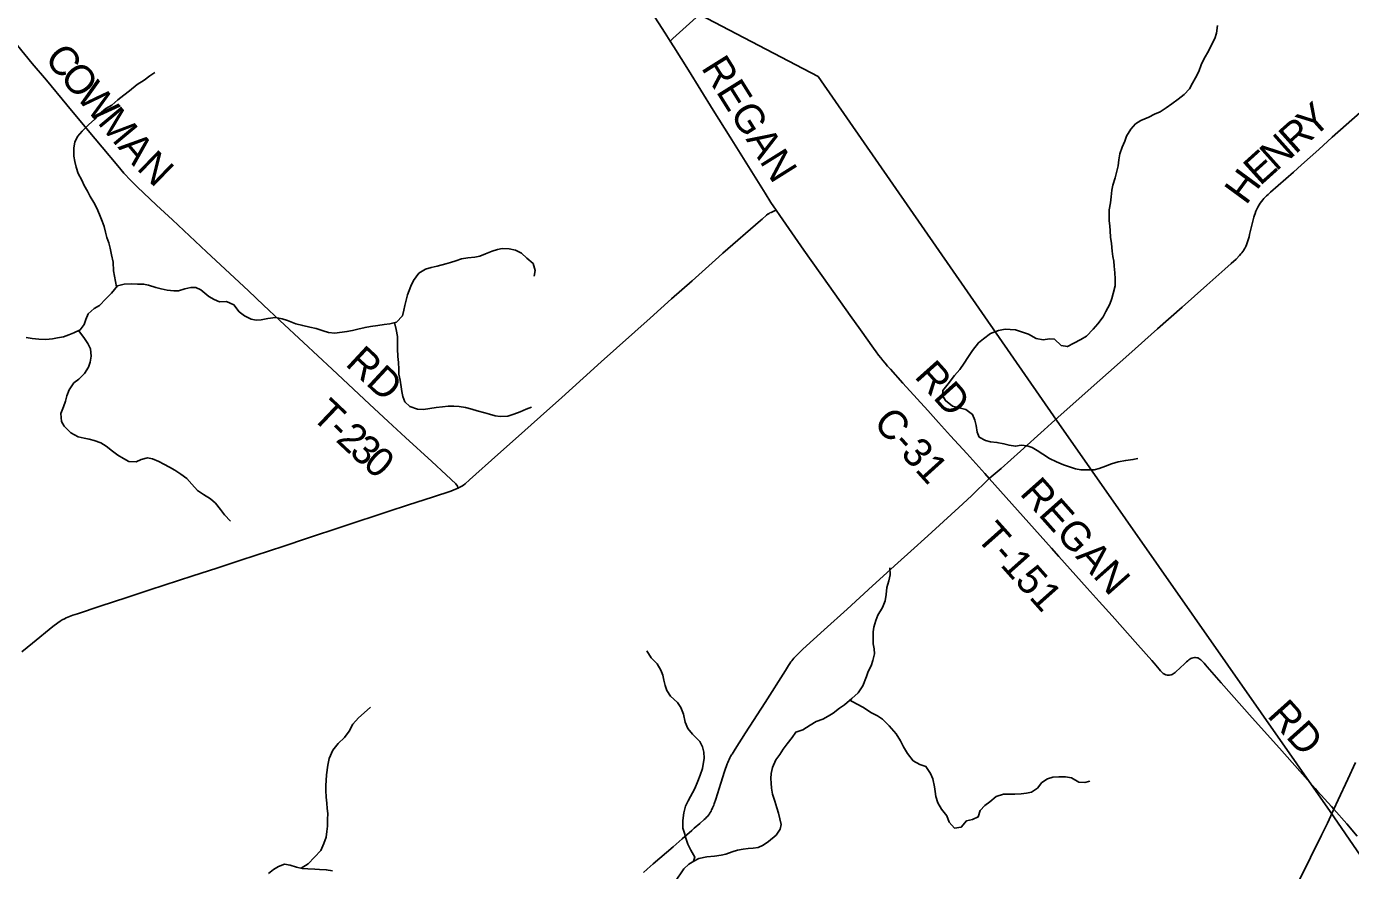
# Model space of a CAD drawing. Extents: x 1442749 to 1756758, y 235267 to 677782.
# Drawn here: x 1623834 to 1637496, y 509882 to 518590 of the extents above; entities that cross this region are included whole.
import ezdxf

# ---------------------------------------------------------------- set-up
doc = ezdxf.new("R2010")
doc.units = 0
for name, color, linetype in [('GM_X_County_Road', 7, 'Continuous'), ('GM_X_County_Road_Text', 7, 'Continuous'), ('GM_X_Minor_River', 7, 'Continuous'), ('GM_X_State_Route', 7, 'Continuous'), ('GM_X_Township', 7, 'Continuous'), ('GM_X_Township_Road', 7, 'Continuous'), ('GM_X_Township_Road_Text', 7, 'Continuous')]:
    doc.layers.add(name, color=color, linetype=linetype)

msp = doc.modelspace()

# ---------------------------------------------------------------- linework, layer by layer
at = {"layer": 'GM_X_County_Road'}
for points in [[(1630476, 518440), (1630423, 518523), (1630288, 518736), (1630140, 518968), (1630068, 519081)], [(1631569, 516694), (1631515, 516775), (1631455, 516869), (1631267, 517173), (1631096, 517449), (1630921, 517727), (1630664, 518139), (1630513, 518381), (1630476, 518440)], [(1637739, 517831), (1637308, 517447), (1637169, 517322), (1636990, 517162), (1636907, 517088), (1636670, 516880), (1636646, 516858), (1636629, 516842), (1636615, 516828), (1636602, 516814), (1636590, 516801), (1636576, 516785), (1636563, 516767), (1636552, 516751), (1636538, 516725), (1636528, 516705), (1636520, 516684), (1636512, 516662), (1636506, 516643), (1636499, 516622), (1636485, 516568), (1636455, 516444), (1636449, 516420), (1636443, 516399), (1636437, 516379), (1636431, 516358), (1636423, 516339), (1636415, 516322), (1636408, 516306), (1636399, 516292), (1636394, 516283), (1636386, 516269), (1636375, 516256), (1636365, 516243), (1636350, 516226), (1636315, 516191), (1636266, 516146), (1636200, 516087), (1636013, 515922), (1635758, 515695), (1635505, 515471), (1635209, 515207), (1634910, 514941), (1634510, 514586), (1634409, 514497), (1634335, 514430)], [(1633768, 513925), (1633721, 513977), (1633537, 514183), (1633369, 514367), (1633246, 514503), (1633133, 514627), (1633024, 514749), (1632875, 514911), (1632748, 515054), (1632718, 515087), (1632693, 515117), (1632669, 515145), (1632648, 515172), (1632627, 515199), (1632601, 515234), (1632574, 515270), (1632440, 515460), (1632333, 515610), (1632118, 515916), (1631855, 516284), (1631606, 516639), (1631569, 516694)], [(1634335, 514430), (1634090, 514210), (1633890, 514029), (1633768, 513925)]]:
    msp.add_lwpolyline(points, dxfattribs=at)
at = {"layer": 'GM_X_Minor_River'}
for points in [[(1636125, 518599), (1636112, 518521), (1636095, 518465), (1636066, 518407), (1636031, 518337), (1635986, 518261), (1635955, 518193), (1635930, 518127), (1635897, 518060), (1635864, 518004), (1635833, 517946), (1635781, 517890), (1635718, 517841), (1635653, 517792), (1635594, 517752), (1635531, 517711), (1635475, 517685), (1635414, 517656), (1635331, 517621), (1635277, 517585), (1635230, 517532), (1635183, 517460), (1635166, 517408), (1635141, 517346), (1635116, 517278), (1635105, 517214), (1635097, 517154), (1635086, 517096), (1635067, 517028), (1635044, 516954), (1635033, 516900), (1635025, 516834), (1635018, 516772), (1635007, 516700), (1635004, 516639), (1635007, 516585), (1635013, 516533), (1635016, 516481), (1635021, 516415), (1635031, 516352), (1635038, 516272), (1635045, 516218), (1635053, 516168), (1635058, 516117), (1635063, 516049), (1635069, 515987), (1635068, 515913), (1635047, 515835), (1635032, 515783), (1635011, 515727), (1634972, 515649)], [(1624764, 515903), (1624741, 516014), (1624732, 516070), (1624727, 516157), (1624710, 516233), (1624697, 516303), (1624683, 516358), (1624664, 516412), (1624648, 516468), (1624635, 516525), (1624616, 516583), (1624588, 516652), (1624561, 516716), (1624530, 516775), (1624492, 516835), (1624463, 516892), (1624429, 516950), (1624404, 517005), (1624368, 517075), (1624345, 517140), (1624332, 517196), (1624322, 517254), (1624321, 517337), (1624334, 517397), (1624361, 517457), (1624408, 517510), (1624475, 517576), (1624540, 517635), (1624587, 517689), (1624654, 517744), (1624714, 517780), (1624777, 517833), (1624838, 517883), (1624897, 517926), (1624976, 517991), (1625049, 518037), (1625106, 518080), (1625160, 518116)], [(1623830, 515380), (1623894, 515370), (1623962, 515363), (1624034, 515362), (1624101, 515369), (1624155, 515379), (1624217, 515390), (1624270, 515408), (1624322, 515429), (1624389, 515462), (1624428, 515514), (1624445, 515568), (1624469, 515626), (1624534, 515681), (1624587, 515713), (1624654, 515780), (1624711, 515840), (1624772, 515913), (1624843, 515933), (1624915, 515936), (1624981, 515933), (1625042, 515933), (1625092, 515922), (1625170, 515897), (1625222, 515882), (1625284, 515870), (1625354, 515863), (1625404, 515864), (1625467, 515884), (1625529, 515897), (1625580, 515896), (1625634, 515874), (1625717, 515805), (1625771, 515772), (1625827, 515751), (1625899, 515752), (1625975, 515719), (1626029, 515647), (1626082, 515606), (1626154, 515569), (1626204, 515560), (1626255, 515564), (1626325, 515577), (1626405, 515588), (1626472, 515575), (1626526, 515557), (1626614, 515524), (1626684, 515505), (1626758, 515488), (1626824, 515473), (1626894, 515450), (1626952, 515432), (1627016, 515427), (1627141, 515442), (1627199, 515455), (1627254, 515468), (1627328, 515486), (1627385, 515495), (1627461, 515506), (1627524, 515516), (1627584, 515523), (1627652, 515540), (1627713, 515604), (1627728, 515662), (1627739, 515712), (1627752, 515766), (1627766, 515822), (1627800, 515912), (1627828, 515971), (1627883, 516045), (1627950, 516086), (1628009, 516104), (1628073, 516119), (1628160, 516142), (1628210, 516156), (1628263, 516173), (1628321, 516193), (1628388, 516202), (1628460, 516209), (1628512, 516219), (1628569, 516246), (1628640, 516271), (1628694, 516289), (1628744, 516300), (1628813, 516295), (1628881, 516281), (1628943, 516252), (1628998, 516201), (1629062, 516144), (1629083, 516072), (1629074, 516014)], [(1634972, 515649), (1634945, 515595), (1634888, 515521), (1634841, 515466), (1634772, 515396), (1634713, 515361), (1634641, 515324), (1634574, 515288), (1634510, 515299), (1634440, 515364), (1634390, 515367), (1634326, 515357), (1634254, 515372), (1634172, 515415), (1634120, 515434), (1634038, 515459), (1633985, 515465), (1633931, 515466), (1633865, 515455), (1633780, 515422), (1633709, 515366), (1633656, 515327), (1633597, 515247), (1633546, 515175), (1633511, 515116), (1633466, 515052), (1633409, 514988), (1633344, 514905), (1633291, 514833), (1633286, 514783), (1633318, 514731), (1633389, 514672), (1633459, 514655), (1633527, 514638), (1633595, 514587), (1633619, 514527), (1633634, 514472), (1633645, 514404), (1633663, 514354), (1633729, 514317), (1633781, 514306), (1633847, 514299), (1633919, 514285), (1633973, 514270), (1634039, 514259), (1634096, 514269), (1634160, 514262), (1634212, 514247), (1634264, 514217), (1634321, 514178), (1634389, 514133), (1634461, 514100), (1634535, 514069), (1634605, 514044), (1634657, 514028), (1634713, 514017), (1634850, 514015), (1634904, 514029), (1634969, 514054), (1635031, 514078), (1635098, 514099), (1635176, 514114), (1635251, 514121), (1635301, 514133)], [(1627631, 515535), (1627647, 515464), (1627663, 515392), (1627662, 515329), (1627663, 515263), (1627666, 515187), (1627671, 515123), (1627677, 515054), (1627676, 515004), (1627689, 514942), (1627699, 514874), (1627706, 514823), (1627719, 514771), (1627737, 514717), (1627789, 514670), (1627869, 514641), (1627929, 514640), (1627995, 514650), (1628060, 514659), (1628126, 514666), (1628186, 514672), (1628245, 514673), (1628297, 514668), (1628363, 514660), (1628429, 514643), (1628485, 514624), (1628563, 514603), (1628613, 514589), (1628669, 514574), (1628723, 514567), (1628802, 514570), (1628862, 514590), (1628929, 514613), (1628989, 514641), (1629046, 514662)], [(1624372, 515454), (1624424, 515382), (1624466, 515319), (1624493, 515263), (1624500, 515188), (1624492, 515126), (1624475, 515074), (1624434, 515009), (1624373, 514953), (1624322, 514912), (1624273, 514840), (1624252, 514778), (1624236, 514726), (1624215, 514666), (1624188, 514598), (1624195, 514516), (1624222, 514465), (1624290, 514398), (1624368, 514355), (1624428, 514343), (1624480, 514334), (1624532, 514319), (1624602, 514293), (1624656, 514260), (1624721, 514207), (1624775, 514166), (1624835, 514132), (1624889, 514101), (1624967, 514100), (1625018, 514121), (1625082, 514139), (1625134, 514128), (1625198, 514101), (1625250, 514073), (1625308, 514044), (1625366, 514013), (1625426, 513970), (1625487, 513928), (1625541, 513867), (1625598, 513804), (1625660, 513761), (1625732, 513718), (1625784, 513672), (1625837, 513607), (1625877, 513552), (1625940, 513485)], [(1631170, 510091), (1631229, 510102), (1631281, 510110), (1631331, 510111), (1631384, 510119), (1631436, 510144), (1631491, 510180), (1631568, 510245), (1631611, 510307), (1631621, 510357), (1631606, 510415), (1631593, 510473), (1631577, 510530), (1631556, 510598), (1631531, 510669), (1631522, 510733), (1631518, 510783), (1631515, 510833), (1631519, 510883), (1631532, 510945), (1631567, 511025), (1631606, 511079), (1631643, 511135), (1631682, 511190), (1631735, 511256), (1631772, 511310), (1631846, 511335), (1631919, 511380), (1631982, 511418), (1632052, 511443), (1632105, 511473), (1632158, 511506), (1632223, 511556), (1632275, 511593), (1632352, 511658), (1632415, 511714), (1632464, 511787), (1632500, 511885), (1632518, 511937), (1632549, 511995), (1632566, 512049), (1632585, 512119), (1632582, 512169), (1632570, 512220), (1632569, 512290), (1632572, 512344), (1632578, 512394), (1632597, 512462), (1632620, 512518), (1632667, 512596), (1632694, 512664), (1632705, 512730), (1632710, 512802), (1632731, 512872), (1632745, 512934), (1632744, 513004)], [(1630718, 509978), (1630731, 510020), (1630690, 510092), (1630659, 510155), (1630639, 510215), (1630624, 510266), (1630606, 510318), (1630605, 510398), (1630618, 510478), (1630635, 510546), (1630660, 510600), (1630730, 510728), (1630761, 510804), (1630784, 510867), (1630809, 510935), (1630826, 511040), (1630823, 511104), (1630809, 511158), (1630782, 511213), (1630707, 511288), (1630659, 511348), (1630632, 511411), (1630613, 511495), (1630587, 511564), (1630550, 511614), (1630480, 511681), (1630441, 511738), (1630423, 511792), (1630410, 511847), (1630399, 511899), (1630379, 511949), (1630342, 512016), (1630280, 512077), (1630235, 512147)], [(1626669, 509905), (1626741, 509952), (1626871, 510087), (1626902, 510159), (1626927, 510227), (1626934, 510285), (1626941, 510339), (1626939, 510407), (1626942, 510471), (1626937, 510523), (1626933, 510576), (1626926, 510638), (1626923, 510706), (1626924, 510756), (1626929, 510869), (1626942, 510969), (1626957, 511039), (1626994, 511123), (1627049, 511194), (1627114, 511254), (1627163, 511321), (1627200, 511391), (1627261, 511459), (1627320, 511510), (1627383, 511567)], [(1632331, 511640), (1632398, 511602), (1632470, 511563), (1632545, 511514), (1632615, 511479), (1632667, 511444), (1632737, 511375), (1632808, 511292), (1632851, 511220), (1632885, 511159), (1632926, 511090), (1632983, 511015), (1633051, 510975), (1633115, 510956), (1633163, 510883), (1633186, 510827), (1633205, 510746), (1633211, 510696), (1633218, 510646), (1633237, 510579), (1633277, 510515), (1633330, 510446), (1633355, 510381), (1633409, 510319), (1633479, 510330), (1633532, 510394), (1633595, 510409), (1633655, 510436), (1633676, 510502), (1633723, 510554), (1633776, 510591), (1633839, 510645), (1633915, 510670), (1633976, 510671), (1634032, 510669), (1634096, 510674), (1634151, 510679), (1634203, 510689), (1634266, 510730), (1634311, 510790), (1634371, 510829), (1634426, 510845), (1634486, 510848), (1634556, 510847), (1634617, 510837), (1634692, 510794), (1634755, 510791), (1634807, 510805)], [(1630523, 509763), (1630617, 509901), (1630670, 509948), (1630721, 509980), (1630773, 510005), (1630854, 510022), (1630934, 510029), (1631001, 510039), (1631051, 510052), (1631116, 510075), (1631170, 510091)], [(1626332, 509852), (1626383, 509892), (1626433, 509923), (1626498, 509947), (1626556, 509938), (1626620, 509915), (1626678, 509903), (1626738, 509900), (1626809, 509895), (1626859, 509892), (1626927, 509890), (1626993, 509877)]]:
    msp.add_lwpolyline(points, dxfattribs=at)
at = {"layer": 'GM_X_State_Route'}
msp.add_lwpolyline([(1636860, 509561), (1637196, 510247), (1637257, 510371), (1637292, 510445), (1637325, 510514), (1637370, 510612), (1637470, 510826), (1637549, 510995)], dxfattribs=at)
at = {"layer": 'GM_X_Township'}
for points in [[(1655741, 500852), (1648788, 495779), (1648023, 495203), (1647406, 496053), (1644427, 500259), (1642919, 502379), (1641006, 505069), (1637287, 510492), (1634462, 514529), (1632004, 518073), (1630779, 518715), (1629985, 519130), (1624968, 521723), (1619669, 524461), (1628661, 526876), (1638146, 529408), (1641622, 530343), (1643929, 530963), (1648625, 532214), (1649470, 532440), (1653261, 533457)], [(1611751, 500101), (1610595, 504741), (1609586, 508788), (1609639, 509167), (1610017, 511903), (1610596, 516202), (1611063, 519742), (1611692, 524289), (1611774, 524885), (1612262, 528413), (1615074, 526905), (1617966, 525366), (1619669, 524461), (1624968, 521723), (1629985, 519130), (1630779, 518715), (1632004, 518073), (1634462, 514529), (1637287, 510492), (1641006, 505069), (1642919, 502379), (1644427, 500259)]]:
    msp.add_lwpolyline(points, dxfattribs=at)
at = {"layer": 'GM_X_Township_Road'}
for points in [[(1630476, 518440), (1630504, 518465), (1630711, 518652), (1630779, 518713)], [(1628288, 513828), (1628285, 513835), (1628280, 513846), (1628274, 513857), (1628271, 513862), (1628264, 513870), (1628164, 513965), (1628017, 514101), (1627746, 514349), (1627567, 514514), (1627373, 514695), (1626987, 515056), (1626692, 515331), (1626449, 515556), (1626280, 515716), (1626125, 515862), (1625884, 516086), (1625690, 516267), (1625340, 516594), (1625175, 516748), (1624976, 516935), (1624911, 517000), (1624839, 517076), (1624775, 517151), (1624614, 517345), (1624472, 517517), (1624252, 517783), (1624039, 518036), (1623894, 518210), (1623664, 518488)], [(1628288, 513828), (1628300, 513833), (1628318, 513843), (1628327, 513848), (1628342, 513859), (1628359, 513871), (1628406, 513912), (1628699, 514175), (1628881, 514336), (1629137, 514566), (1629357, 514763), (1629579, 514962), (1629765, 515129), (1630268, 515580), (1630491, 515779), (1630702, 515967), (1630978, 516213), (1631019, 516250), (1631407, 516590), (1631424, 516604), (1631470, 516643), (1631487, 516656), (1631491, 516659), (1631497, 516662), (1631505, 516667), (1631517, 516672), (1631547, 516685), (1631569, 516694)], [(1630200, 509861), (1630239, 509896), (1630300, 509950), (1630506, 510128), (1630601, 510209), (1630699, 510296), (1630724, 510318), (1630781, 510367), (1630828, 510409), (1630839, 510420), (1630847, 510428), (1630863, 510444), (1630872, 510454), (1630881, 510466), (1630890, 510479), (1630898, 510493), (1630904, 510507), (1630909, 510517), (1630914, 510529), (1630919, 510541), (1630925, 510556), (1630930, 510569), (1630946, 510619), (1630998, 510782), (1631037, 510904), (1631065, 510984), (1631070, 510997), (1631077, 511014), (1631084, 511029), (1631093, 511045), (1631100, 511059), (1631109, 511075), (1631115, 511084), (1631145, 511133), (1631254, 511301), (1631456, 511616), (1631665, 511946), (1631697, 511998), (1631709, 512018), (1631720, 512034), (1631730, 512045), (1631741, 512059), (1631752, 512072), (1631770, 512091), (1631799, 512121), (1631846, 512166), (1632064, 512365), (1632301, 512579), (1632565, 512820), (1632825, 513055), (1632958, 513177), (1633133, 513336), (1633295, 513484), (1633453, 513628), (1633584, 513747), (1633768, 513925)], [(1633768, 513925), (1633944, 513732), (1634236, 513403), (1634411, 513207), (1634487, 513121), (1634778, 512796), (1634903, 512657), (1635035, 512511), (1635302, 512212), (1635445, 512049), (1635469, 512022), (1635522, 511960), (1635536, 511942), (1635545, 511933), (1635554, 511924), (1635564, 511916), (1635578, 511908), (1635592, 511902), (1635604, 511899), (1635615, 511896), (1635628, 511897), (1635644, 511900), (1635656, 511905), (1635666, 511910), (1635678, 511917), (1635687, 511926), (1635702, 511938), (1635731, 511965), (1635790, 512022), (1635804, 512036), (1635816, 512046), (1635827, 512056), (1635838, 512063), (1635848, 512069), (1635859, 512074), (1635872, 512077), (1635885, 512079), (1635897, 512079), (1635909, 512077), (1635920, 512075), (1635926, 512072), (1635931, 512070), (1635941, 512062), (1635950, 512055), (1635965, 512042), (1635986, 512020), (1635999, 512005), (1636017, 511985), (1636163, 511817), (1636481, 511459), (1636763, 511143), (1637132, 510729), (1637156, 510702), (1637301, 510541), (1637325, 510514)], [(1623787, 512139), (1623896, 512229), (1624105, 512398), (1624159, 512438), (1624180, 512453), (1624203, 512467), (1624225, 512479), (1624243, 512488), (1624262, 512496), (1624279, 512504), (1624311, 512515), (1624360, 512532), (1624594, 512608), (1624871, 512700), (1625108, 512778), (1625551, 512922), (1625797, 513003), (1626046, 513085), (1626489, 513230), (1626723, 513306), (1627097, 513430), (1627577, 513588), (1627764, 513650), (1628035, 513737), (1628213, 513796), (1628261, 513815), (1628288, 513828)], [(1637325, 510514), (1637457, 510364), (1637566, 510237)]]:
    msp.add_lwpolyline(points, dxfattribs=at)

# ---------------------------------------------------------------- texts
at = {"layer": 'GM_X_County_Road_Text'}
for s, rotation, p in [('REGAN', 302.0453, (1630790, 518165)), ('Y', 41.7648, (1637110, 517430)), ('R', 41.7554, (1636926, 517266)), ('N', 41.7606, (1636729, 517090)), ('E', 42.0563, (1636563, 516940)), ('H', 53.761, (1636418, 516739)), ('RD', 311.84, (1632987, 514974)), ('C-31', 312.0926, (1632561, 514493))]:
    msp.add_text(s, height=300, rotation=rotation, dxfattribs=at).set_placement(p)
at = {"layer": 'GM_X_Township_Road_Text'}
for s, rotation, p in [('C', 309.7796, (1624010, 518256)), ('O', 309.7851, (1624168, 518067)), ('W', 309.7829, (1624337, 517864)), ('M', 309.7799, (1624559, 517597)), ('A', 310.3433, (1624770, 517344)), ('N', 315.9467, (1624962, 517120)), ('RD', 317.0941, (1627114, 515100)), ('T', 316.4669, (1626763, 514557)), ('-', 316.5451, (1626926, 514402)), ('2', 316.8554, (1627016, 514317)), ('3', 317.4312, (1627154, 514188)), ('0', 318.503, (1627294, 514059)), ('REGAN', 311.6322, (1634074, 513768)), ('T-151', 311.6778, (1633622, 513314)), ('RD', 311.8748, (1636627, 511475))]:
    msp.add_text(s, height=300, rotation=rotation, dxfattribs=at).set_placement(p)

doc.saveas('drawing.dxf')
